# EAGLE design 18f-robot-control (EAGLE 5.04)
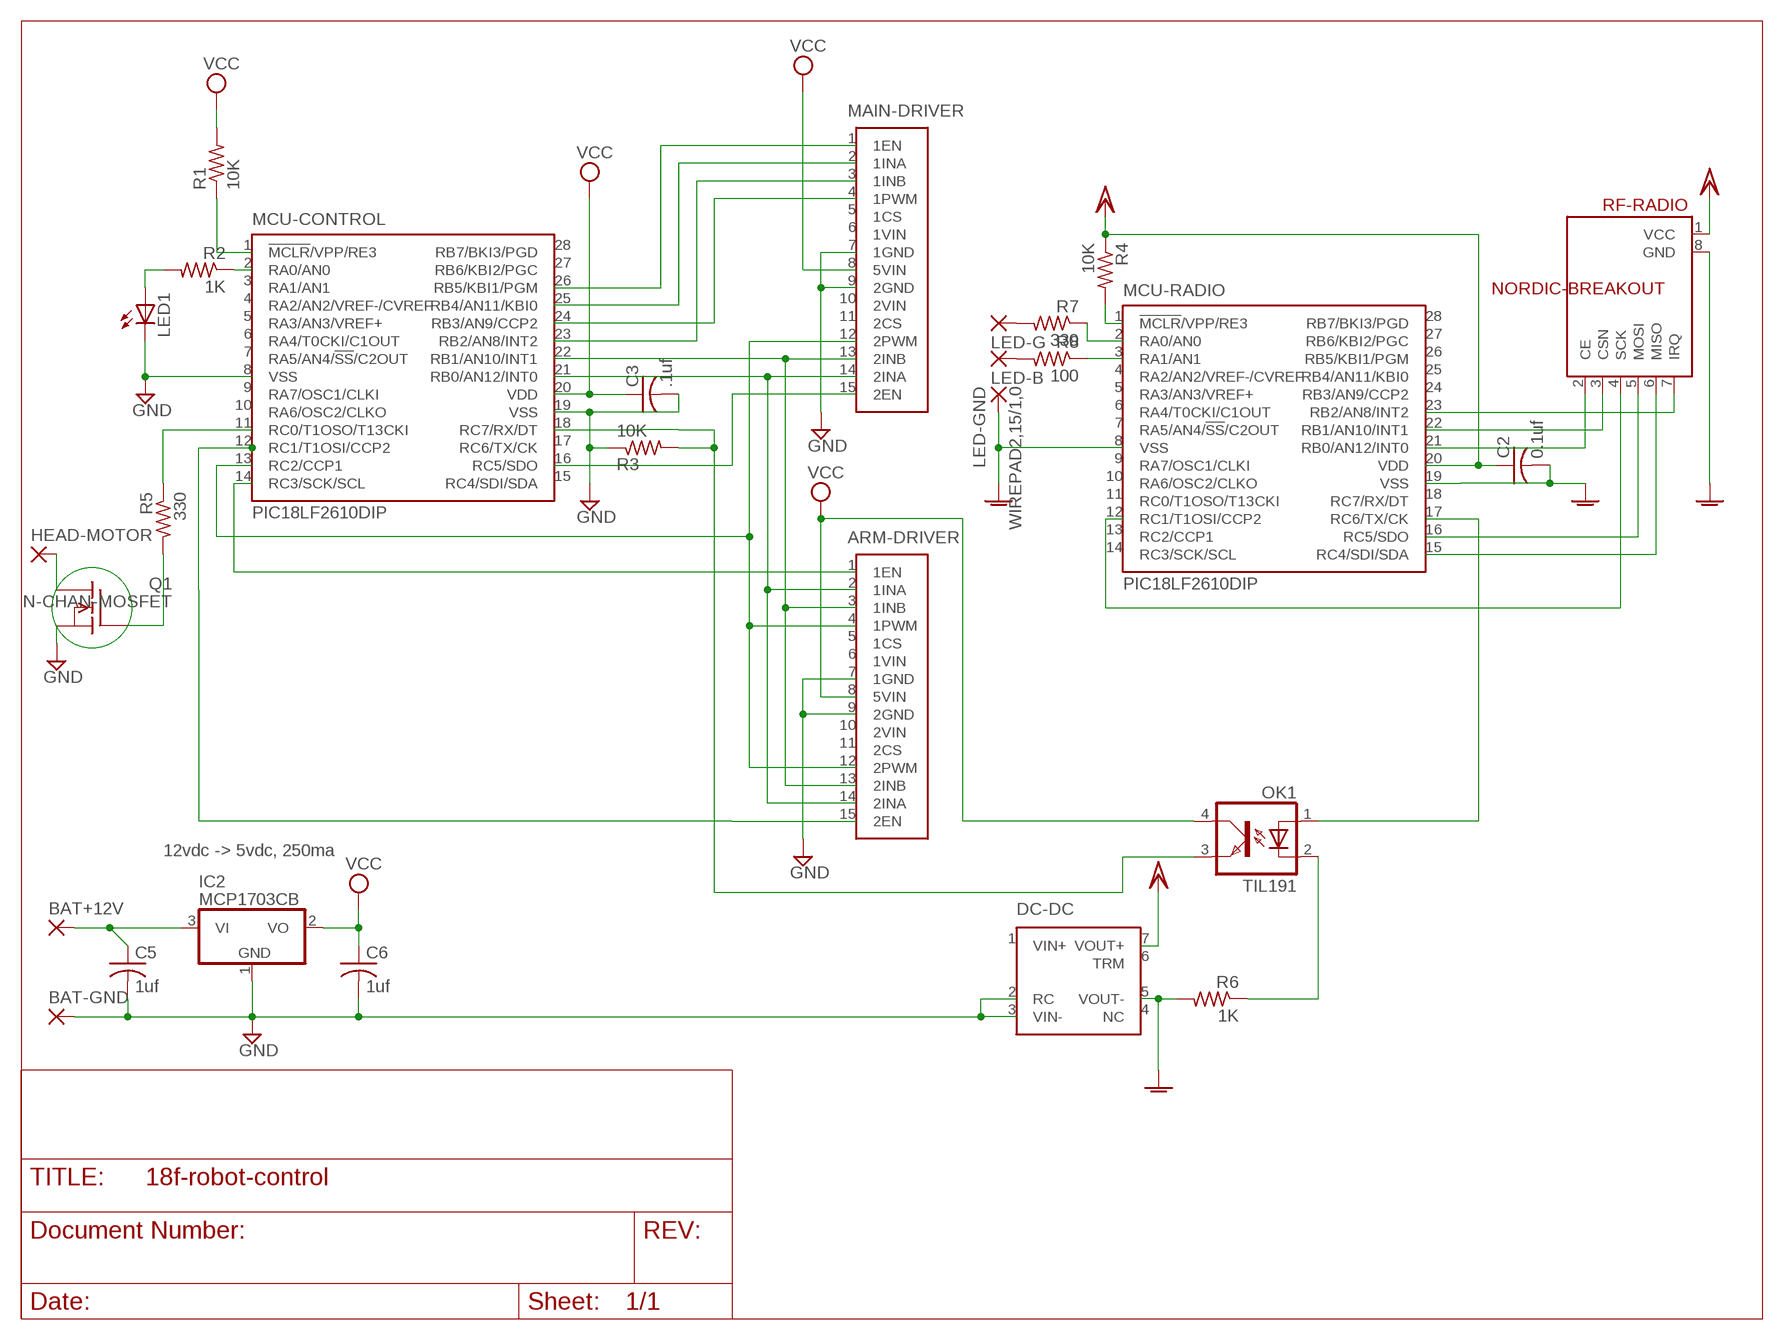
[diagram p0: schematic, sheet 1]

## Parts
ARM-DRIVER  POLOLU-DUAL-DRIVER-15ONLY  [15SIL]
BAT+12V  WIREPAD3,81/1,4  [3,81/1,4]
BAT-GND  WIREPAD3,81/1,4  [3,81/1,4]
C2  0.1uf  C-US050-030X075  [C050-030X075]
C3  .1uf  C-US025-030X050  [C025-030X050]
C5  1uf  C-US050-030X075  [C050-030X075]
C6  1uf  C-US050-030X075  [C050-030X075]
DC-DC  12V-5V-ISOLATED-DC-DC-TDK-LAMBDA  [DC-DC-12-5-TDK-LAMBDA]
HEAD-MOTOR  3,81/1,4  [3,81/1,4]
IC2  MCP1703CB  [SOT23]
LED1  LEDSFH480  [SFH480]
LED-B  WIREPAD2,15/1,0  [2,15/1,0]
LED-G  WIREPAD2,15/1,0  [2,15/1,0]
LED-GND  WIREPAD2,15/1,0  [2,15/1,0]
MAIN-DRIVER  POLOLU-DUAL-DRIVER-15ONLY  [15SIL]
MCU-CONTROL  PIC18LF2610DIP  [DIL28-3]
MCU-RADIO  PIC18LF2610DIP  [DIL28-3]
OK1  TIL191  [DIL04]
Q1  N-CHAN-MOSFET  SUP75N06-08  [TO220]
R1  10K  R-US_0204/7  [0204/7]
R2  1K  R-US_0204/7  [0204/7]
R3  10K  R-US_0204/7  [0204/7]
R4  10K  R-US_0204/7  [0204/7]
R5  330  R-US_0204/7  [0204/7]
R6  1K  R-US_0204/7  [0204/7]
R7  330  R-US_0204/7  [0204/7]
R8  100  R-US_0204/7  [0204/7]
RF-RADIO  NORDIC-BREAKOUT  [8SIL]

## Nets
GND: ARM-DRIVER.7(1GND) ARM-DRIVER.9(2GND) BAT-GND.1(P) C3.2 C5.2 C6.2 DC-DC.2(RC) DC-DC.3(VIN-) IC2.1(GND) LED1.K(C) MAIN-DRIVER.7(1GND) MAIN-DRIVER.9(2GND) MCU-CONTROL.8(VSS) MCU-CONTROL.19(VSS) Q1.3(S) R3.1
GND2: C2.2 DC-DC.5(VOUT-) LED-GND.1(P) MCU-RADIO.8(VSS) MCU-RADIO.19(VSS) R6.2 RF-RADIO.8(GND)
N$1: LED1.A R2.2
N$2: MCU-CONTROL.2(RA0/AN0) R2.1
N$3: HEAD-MOTOR.1(P) Q1.2(D)
N$4: ARM-DRIVER.15(2EN) MCU-CONTROL.12(RC1/T1OSI/CCP2)
N$5: MCU-CONTROL.11(RC0/T1OSO/T13CKI) R5.1
N$6: MCU-RADIO.2(RA0/AN0) R7.1
N$7: OK1.2(C) R6.1
N$8: MCU-RADIO.17(RC6/TX/CK) OK1.1(A)
N$9: MCU-CONTROL.18(RC7/RX/DT) OK1.3(EMIT) R3.2
N$10: MCU-RADIO.15(RC4/SDI/SDA) RF-RADIO.6(MISO)
N$11: MCU-RADIO.16(RC5/SDO) RF-RADIO.5(MOSI)
N$12: MAIN-DRIVER.4(1PWM) MCU-CONTROL.24(RB3/AN9/CCP2)
N$13: ARM-DRIVER.4(1PWM) ARM-DRIVER.12(2PWM) MAIN-DRIVER.12(2PWM) MCU-CONTROL.13(RC2/CCP1)
N$14: MCU-RADIO.12(RC1/T1OSI/CCP2) RF-RADIO.4(SCK)
N$15: ARM-DRIVER.1(1EN) MCU-CONTROL.14(RC3/SCK/SCL)
N$16: Q1.1(G) R5.2
N$17: MCU-RADIO.1(!MCLR!/VPP/RE3) R4.2
N$18: ARM-DRIVER.2(1INA) ARM-DRIVER.14(2INA) MAIN-DRIVER.14(2INA) MCU-CONTROL.21(RB0/AN12/INT0)
N$19: MCU-RADIO.22(RB1/AN10/INT1) RF-RADIO.3(CSN)
N$21: MAIN-DRIVER.2(1INA) MCU-CONTROL.25(RB4/AN11/KBI0)
N$22: MAIN-DRIVER.3(1INB) MCU-CONTROL.23(RB2/AN8/INT2)
N$23: MCU-RADIO.23(RB2/AN8/INT2) RF-RADIO.7(IRQ)
N$24: MAIN-DRIVER.15(2EN) MCU-CONTROL.16(RC5/SDO)
N$25: MCU-RADIO.21(RB0/AN12/INT0) RF-RADIO.2(CE)
N$26: MCU-RADIO.3(RA1/AN1) R8.1
N$28: MCU-CONTROL.1(!MCLR!/VPP/RE3) R1.1
N$31: MAIN-DRIVER.1(1EN) MCU-CONTROL.26(RB5/KBI1/PGM)
N$33: LED-G.1(P) R7.2
N$34: LED-B.1(P) R8.2
N$35: BAT+12V.1(P) C5.1 IC2.3(VI)
N$54: ARM-DRIVER.3(1INB) ARM-DRIVER.13(2INB) MAIN-DRIVER.13(2INB) MCU-CONTROL.22(RB1/AN10/INT1)
VCC: ARM-DRIVER.8(5VIN) C3.1 C6.1 IC2.2(VO) MAIN-DRIVER.8(5VIN) MCU-CONTROL.20(VDD) OK1.4(COL) R1.2
VCC2: C2.1 DC-DC.7(VOUT+) MCU-RADIO.20(VDD) R4.1 RF-RADIO.1(VCC)
Unconnected: ARM-DRIVER.5(1CS) ARM-DRIVER.6(1VIN) ARM-DRIVER.10(2VIN) ARM-DRIVER.11(2CS) DC-DC.1(VIN+) DC-DC.4(NC) DC-DC.6(TRM) MAIN-DRIVER.5(1CS) MAIN-DRIVER.6(1VIN) MAIN-DRIVER.10(2VIN) MAIN-DRIVER.11(2CS) MCU-CONTROL.3(RA1/AN1) MCU-CONTROL.4(RA2/AN2/VREF-/CVREF) MCU-CONTROL.5(RA3/AN3/VREF+) MCU-CONTROL.6(RA4/T0CKI/C1OUT) MCU-CONTROL.7(RA5/AN4/!SS!/C2OUT) MCU-CONTROL.9(RA7/OSC1/CLKI) MCU-CONTROL.10(RA6/OSC2/CLKO) MCU-CONTROL.15(RC4/SDI/SDA) MCU-CONTROL.17(RC6/TX/CK) MCU-CONTROL.27(RB6/KBI2/PGC) MCU-CONTROL.28(RB7/BKI3/PGD) MCU-RADIO.4(RA2/AN2/VREF-/CVREF) MCU-RADIO.5(RA3/AN3/VREF+) MCU-RADIO.6(RA4/T0CKI/C1OUT) MCU-RADIO.7(RA5/AN4/!SS!/C2OUT) MCU-RADIO.9(RA7/OSC1/CLKI) MCU-RADIO.10(RA6/OSC2/CLKO) MCU-RADIO.11(RC0/T1OSO/T13CKI) MCU-RADIO.13(RC2/CCP1) MCU-RADIO.14(RC3/SCK/SCL) MCU-RADIO.18(RC7/RX/DT) MCU-RADIO.24(RB3/AN9/CCP2) MCU-RADIO.25(RB4/AN11/KBI0) MCU-RADIO.26(RB5/KBI1/PGM) MCU-RADIO.27(RB6/KBI2/PGC) MCU-RADIO.28(RB7/BKI3/PGD)

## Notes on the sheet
- 12vdc -> 5vdc, 250ma

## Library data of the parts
ARM-DRIVER MAIN-DRIVER = trl:POLOLU-DUAL-DRIVER-15ONLY
BAT+12V BAT-GND LED-B LED-G LED-GND = wirepad:WIREPAD: Wire PAD connect wire on PCB
C2 C3 C5 C6 = rcl:C-US: CAPACITOR, American symbol
DC-DC = trl:12V-5V-ISOLATED-DC-DC-TDK-LAMBDA
HEAD-MOTOR = wirepad:3,81/1,4: THROUGH-HOLE PAD
IC2 = linear:MCP1703: 250 mA, 16V, Low Quiescent Current LDO Regulator Source: http://ww1.microchip.com/downloads/en/DeviceDoc/22049b.pdf
LED1 = led:LED: LED
MCU-CONTROL MCU-RADIO = trl:PIC18LF2610: PIC18LF2610 28-Pin, No USB or EEPROM
OK1 = optocoupler:TIL191: TEXAS INSTRUMENTS OPTO COUPLER
Q1 = transistor-fet:SUP75N06-08: N-Channel Enhancement MOSFET 60V; 75A; 0,008Ohm
R1-R8 = resistor:R-US_: RESISTOR, American symbol
RF-RADIO = trl:NORDIC-BREAKOUT: Spark Fun Electronic's Nordic Semiconductor nRF24L01 with chip antenna

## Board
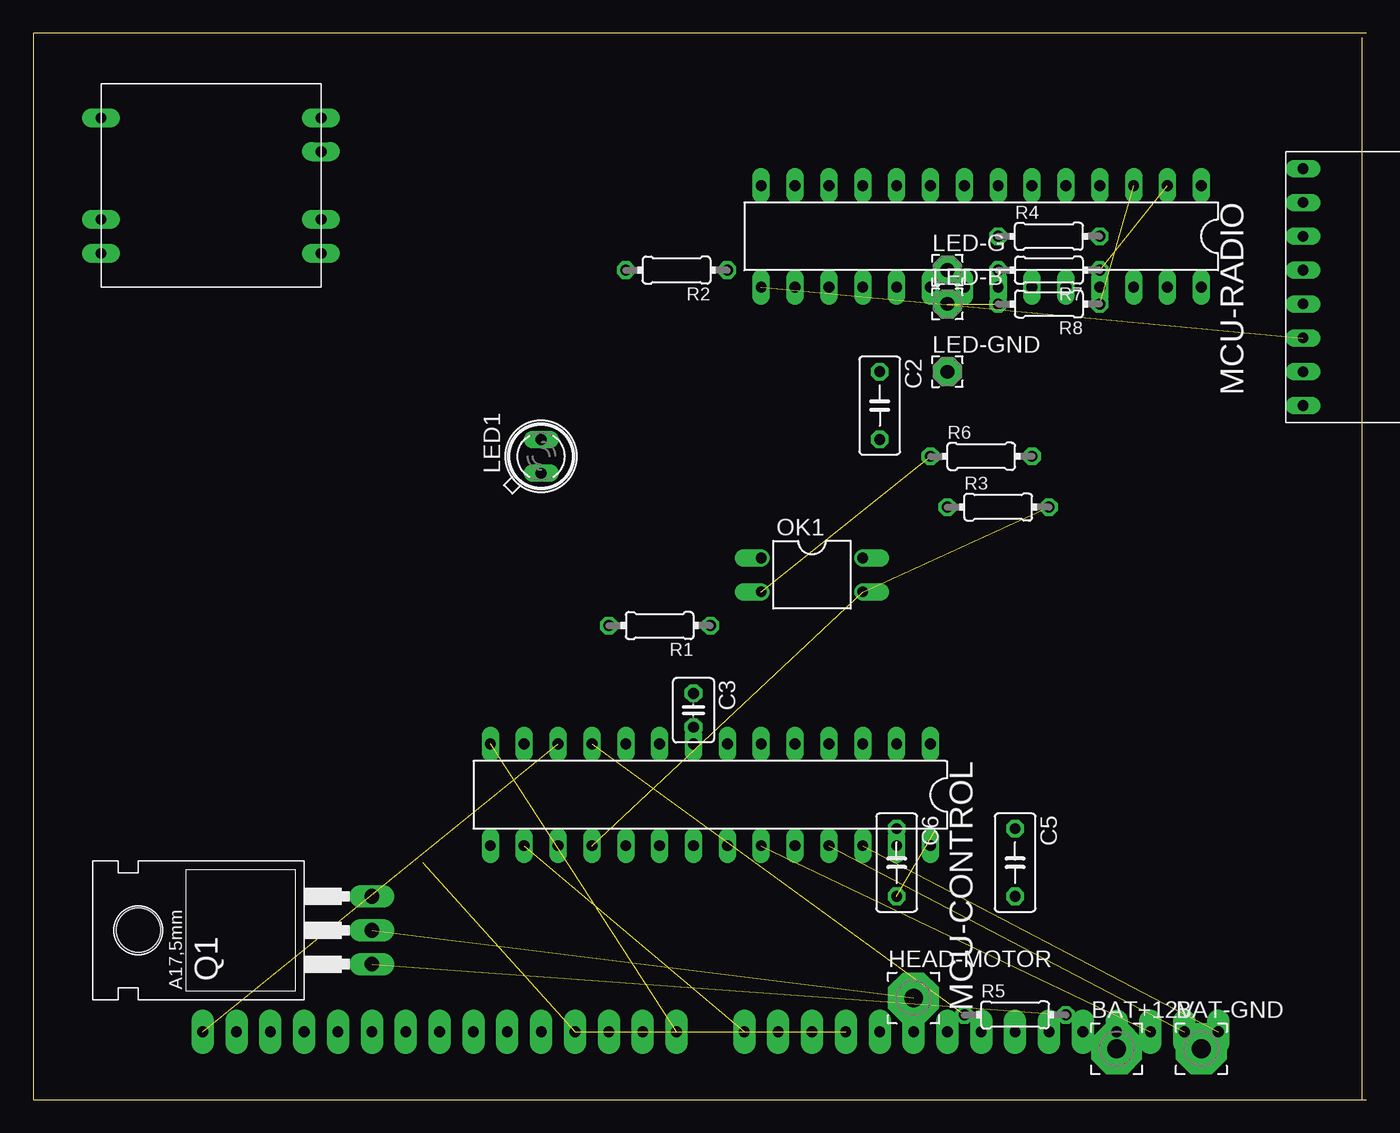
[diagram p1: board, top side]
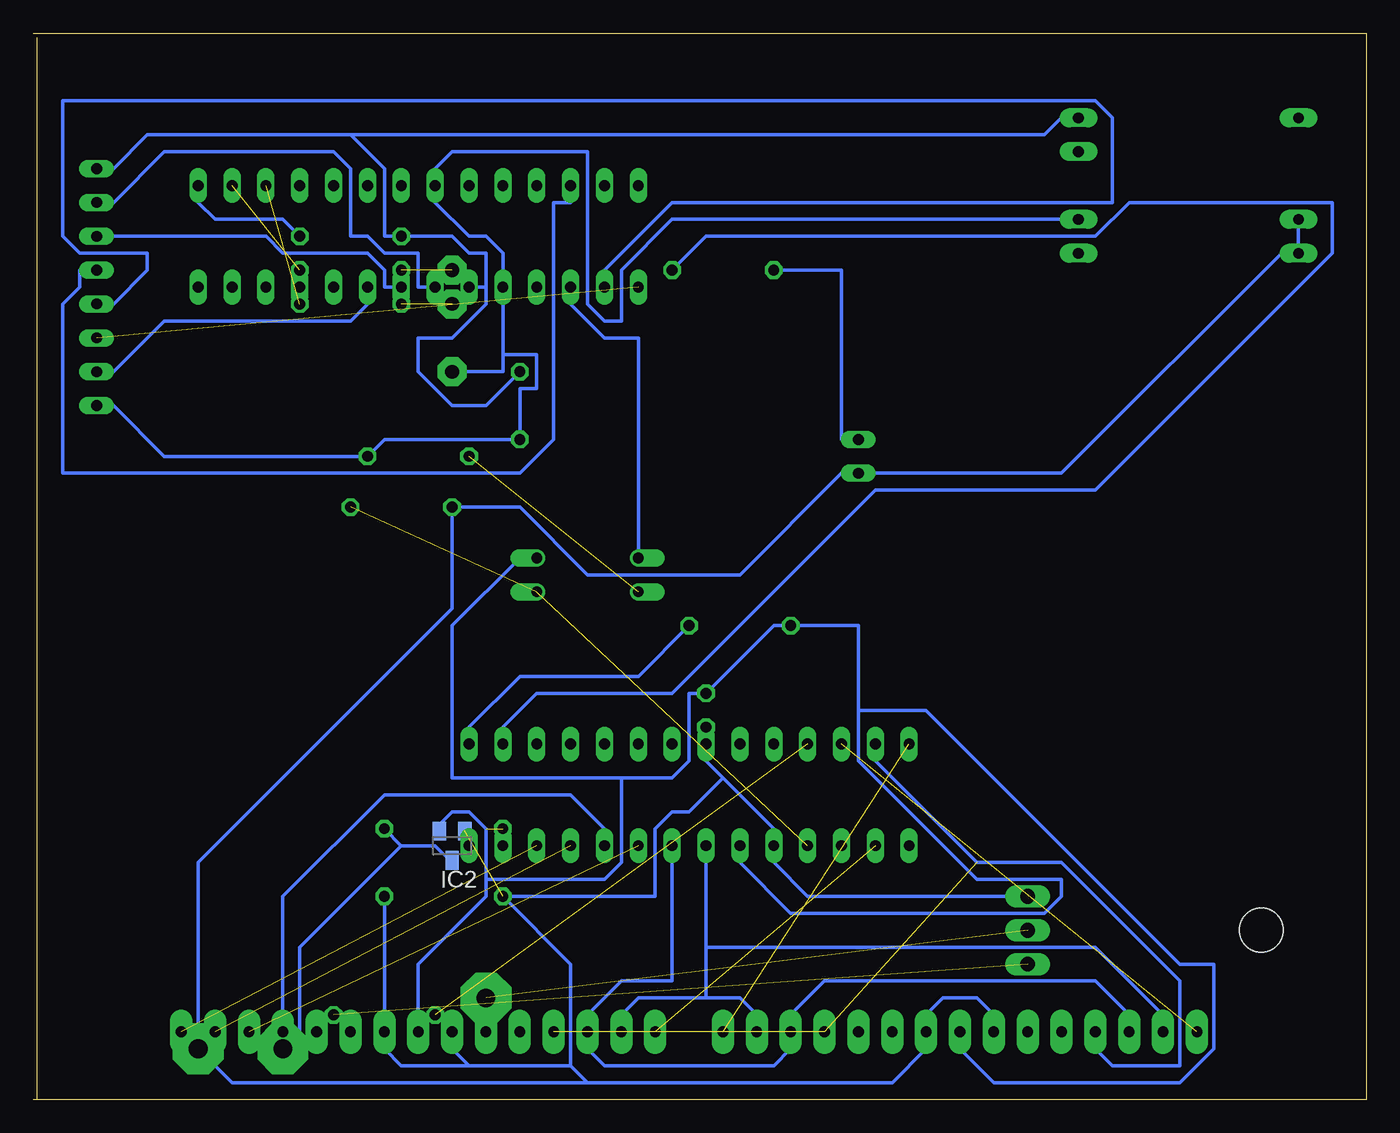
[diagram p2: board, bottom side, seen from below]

Size 100 x 80 mm. Coordinates in mm from the lower left corner, seen from the top.
Outline: 99.69,0 0,0 0,80 100,80
Outline: 99.69,0 100,0
Outline: 99.69,0 99.69,79.68
Copper layers (1*16): Top 0.035mm / dielectric 1.5mm / Bottom 0.035mm
Design rules "default": minimum track width 10mil, minimum drill 24mil, track to track 8mil, track to pad 8mil, pad to pad 8mil, via to via 8mil, smd to smd 8mil, copper to edge 40mil, drill to drill 8mil, minimum pad ring 10mil, minimum via ring 8mil, stop-mask expansion 4mil, vias tented up to drill 0mil, thermal gap 10mil

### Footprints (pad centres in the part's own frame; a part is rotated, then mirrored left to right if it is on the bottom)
15SIL = drill 0.8 pad 1.676 long: 1 -17.78,0; 2 -15.24,0; 3 -12.7,0; 4 -10.16,0; 5 -7.62,0; 6 -5.08,0; 7 -2.54,0; 8 0,0; 9 2.54,0; 10 5.08,0; 11 7.62,0; 12 10.16,0; 13 12.7,0; 14 15.24,0; 15 17.78,0
3,81/1,4 = drill 1.397 pad 3.81 octagon: 1 0,0
C050-030X075 = drill 0.813 octagon: 1 -2.54,0; 2 2.54,0
C025-030X050 = drill 0.813 octagon: 1 -1.27,0; 2 1.27,0
DC-DC-12-5-TDK-LAMBDA = drill 0.8 pad 1.422 long: 1 -8.89,5.08; 2 -8.89,-2.54; 3 -8.89,-5.08; 4 7.62,-5.08; 5 7.62,-2.54; 6 7.62,2.54; 7 7.62,5.08
SOT23 = smd 1 x 1.4: 1 -0.95,-1.1; 2 0.95,-1.1; 3 0,1.1
SFH480 = drill 0.813 long: A 1.27,0; K -1.27,0
2,15/1,0 = drill 1.016 pad 2.159 octagon: 1 0,0
DIL28-3 = drill 0.813 long: 1 -16.51,-3.81; 2 -13.97,-3.81; 3 -11.43,-3.81; 4 -8.89,-3.81; 5 -6.35,-3.81; 6 -3.81,-3.81; 7 -1.27,-3.81; 8 1.27,-3.81; 9 3.81,-3.81; 10 6.35,-3.81; 11 8.89,-3.81; 12 11.43,-3.81; 13 13.97,-3.81; 14 16.51,-3.81; 15 16.51,3.81; 16 13.97,3.81; 17 11.43,3.81; 18 8.89,3.81; 19 6.35,3.81; 20 3.81,3.81; 21 1.27,3.81; 22 -1.27,3.81; 23 -3.81,3.81; 24 -6.35,3.81; 25 -8.89,3.81; 26 -11.43,3.81; 27 -13.97,3.81; 28 -16.51,3.81
DIL04 = drill 0.813 offset: 1 -1.27,-3.81; 2 1.27,-3.81; 3 1.27,3.81; 4 -1.27,3.81
TO220 = drill 1.118 long: 1 -2.54,-6.35; 2 0,-6.35; 3 2.54,-6.35 | hole 3.302: 0,11.176
0204/7 = drill 0.813 octagon: 1 -3.81,0; 2 3.81,0
8SIL = drill 0.8 long: 1 -8.89,-8.89; 2 -6.35,-8.89; 3 -3.81,-8.89; 4 -1.27,-8.89; 5 1.27,-8.89; 6 3.81,-8.89; 7 6.35,-8.89; 8 8.89,-8.89

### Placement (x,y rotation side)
ARM-DRIVER  30.48,5.08 180 top
BAT+12V  81.28,3.81 0 top
BAT-GND  87.63,3.81 0 top
C2  63.5,52.07 270 top
C3  49.53,29.21 270 top
C5  73.66,17.78 270 top
C6  64.77,17.78 270 top
DC-DC  13.97,68.58 0 top
HEAD-MOTOR  66.04,7.62 0 top
IC2  68.58,19.05 180 bottom
LED1  38.1,48.26 90 top
LED-B  68.58,59.69 0 top
LED-G  68.58,62.23 0 top
LED-GND  68.58,54.61 0 top
MAIN-DRIVER  71.12,5.08 180 top
MCU-CONTROL  50.8,22.86 180 top
MCU-RADIO  71.12,64.77 180 top
OK1  58.42,39.37 270 top
Q1  19.05,12.7 90 top
R1  46.99,35.56 180 top
R2  48.26,62.23 180 top
R3  72.39,44.45 0 top
R4  76.2,64.77 0 top
R5  73.66,6.35 0 top
R6  71.12,48.26 0 top
R7  76.2,62.23 180 top
R8  76.2,59.69 180 top
RF-RADIO  104.14,60.96 270 top

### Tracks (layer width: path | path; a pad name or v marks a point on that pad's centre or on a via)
GND  (1 unrouted)
  Bottom 0.254: DC-DC.2 DC-DC.3 6.35,63.5 22.86,46.99 36.83,46.99 LED1.K 39.37,46.99 46.99,39.37 58.42,39.37 63.5,44.45 R3.1 68.58,36.83 87.63,17.78 87.63,5.08 BAT-GND.1 86.36,2.54 85.09,1.27 58.42,1.27 | 48.26,24.13 49.53,25.4 MCU-CONTROL.8 C3.2 | 48.26,24.13 44.45,20.32 MCU-CONTROL.19 44.45,17.78 41.91,15.24 26.67,15.24 Q1.3 | C5.2 73.66,6.35 MAIN-DRIVER.7 73.66,3.81 72.39,2.54 67.31,2.54 | ARM-DRIVER.9 27.94,6.35 29.21,7.62 31.75,7.62 33.02,6.35 ARM-DRIVER.7 33.02,3.81 35.56,1.27 58.42,1.27 | 59.69,2.54 59.69,10.16 C6.2 53.34,15.24 53.34,20.32 52.07,21.59 50.8,21.59 48.26,24.13 | 59.69,2.54 67.31,2.54 | 67.31,2.54 68.58,3.81 MAIN-DRIVER.9 | 58.42,1.27 59.69,2.54
GND2
  Bottom 0.254: RF-RADIO.8 93.98,52.07 90.17,48.26 R6.2 73.66,49.53 C2.2 63.5,53.34 62.23,53.34 62.23,55.88 64.77,55.88 | 64.77,55.88 64.77,54.61 LED-GND.1 | 64.77,55.88 64.77,59.69 MCU-RADIO.19 64.77,62.23 64.77,63.5 66.04,64.77 67.31,64.77 69.85,67.31 MCU-RADIO.8 69.85,69.85 68.58,71.12 58.42,71.12 58.42,59.69 57.15,58.42 55.88,58.42 55.88,62.23 52.07,66.04 22.86,66.04 DC-DC.5
N$1
  Bottom 0.254: R2.2 39.37,62.23 39.37,49.53 LED1.A
N$2
  Bottom 0.254: R2.1 49.53,64.77 20.32,64.77 17.78,67.31 2.54,67.31 2.54,63.5 20.32,45.72 36.83,45.72 52.07,30.48 62.23,30.48 64.77,27.94 MCU-CONTROL.2
N$3  (1 unrouted)
N$4  (1 unrouted)
N$5  (1 unrouted)
N$6  (1 unrouted)
N$7  (1 unrouted)
N$8
  Bottom 0.254: OK1.1 54.61,57.15 57.15,57.15 59.69,59.69 MCU-RADIO.17
N$9  (2 unrouted)
N$10  (1 unrouted)
N$11
  Bottom 0.254: RF-RADIO.5 93.98,59.69 91.44,62.23 91.44,63.5 96.52,63.5 97.79,64.77 97.79,74.93 20.32,74.93 19.05,73.66 19.05,67.31 52.07,67.31 57.15,62.23 MCU-RADIO.16
N$12
  Bottom 0.254: MCU-CONTROL.24 57.15,20.32 59.69,22.86 73.66,22.86 81.28,15.24 81.28,6.35 MAIN-DRIVER.4
N$13  (2 unrouted)
  Bottom 0.254: MCU-CONTROL.13 36.83,25.4 29.21,17.78 22.86,17.78 13.97,8.89 13.97,2.54 19.05,2.54 20.32,3.81 ARM-DRIVER.12
N$14
  Bottom 0.254: RF-RADIO.4 96.52,62.23 96.52,60.96 97.79,59.69 97.79,46.99 63.5,46.99 60.96,49.53 60.96,67.31 59.69,67.31 MCU-RADIO.12
N$15  (1 unrouted)
N$16  (1 unrouted)
N$17
  Bottom 0.254: R4.2 81.28,66.04 86.36,66.04 87.63,67.31 MCU-RADIO.1
N$18
  Bottom 0.254: 49.53,11.43 49.53,7.62 | 49.53,11.43 49.53,17.78 MCU-CONTROL.21 | 49.53,7.62 46.99,7.62 45.72,6.35 ARM-DRIVER.2 | 49.53,11.43 20.32,11.43 15.24,6.35 ARM-DRIVER.14 | 49.53,7.62 54.61,7.62 55.88,6.35 MAIN-DRIVER.14
N$19
  Bottom 0.254: MCU-RADIO.22 73.66,60.96 73.66,62.23 74.93,63.5 81.28,63.5 82.55,64.77 93.98,64.77 RF-RADIO.3
N$21  (1 unrouted)
N$22  (1 unrouted)
N$23
  Bottom 0.254: RF-RADIO.7 93.98,54.61 90.17,58.42 76.2,58.42 74.93,59.69 MCU-RADIO.23
N$24  (1 unrouted)
N$25
  Bottom 0.254: MCU-RADIO.21 71.12,60.96 71.12,63.5 73.66,63.5 74.93,64.77 76.2,64.77 76.2,69.85 77.47,71.12 90.17,71.12 93.98,67.31 RF-RADIO.2
N$26  (1 unrouted)
N$28
  Bottom 0.254: R1.1 54.61,31.75 63.5,31.75 67.31,27.94 MCU-CONTROL.1
N$31  (1 unrouted)
N$33  (1 unrouted)
N$34  (1 unrouted)
N$35
  Bottom 0.254: 72.39,19.05 69.85,19.05 68.58,17.78 IC2.3 | 72.39,19.05 C5.1 | 72.39,19.05 80.01,11.43 80.01,5.08 BAT+12V.1
N$54
  Bottom 0.254: MCU-CONTROL.22 52.07,17.78 52.07,8.89 55.88,8.89 58.42,6.35 MAIN-DRIVER.13 58.42,3.81 57.15,2.54 44.45,2.54 43.18,3.81 ARM-DRIVER.3 43.18,6.35 40.64,8.89 20.32,8.89 17.78,6.35 ARM-DRIVER.13
VCC  (1 unrouted)
  Bottom 0.254: 66.04,16.51 66.04,15.24 71.12,10.16 71.12,6.35 MAIN-DRIVER.8 | 66.04,16.51 66.04,20.32 67.31,21.59 68.58,21.59 69.85,20.32 IC2.2 | 38.1,29.21 38.1,35.56 R1.2 44.45,35.56 C3.1 50.8,30.48 50.8,25.4 52.07,24.13 55.88,24.13 | 38.1,29.21 38.1,25.4 29.21,16.51 22.86,16.51 22.86,15.24 24.13,13.97 43.18,13.97 46.99,17.78 MCU-CONTROL.20 | 55.88,24.13 68.58,24.13 68.58,35.56 63.5,40.64 OK1.4 | 38.1,29.21 33.02,29.21 13.97,10.16 11.43,10.16 11.43,3.81 13.97,1.27 27.94,1.27 30.48,3.81 ARM-DRIVER.8 | 66.04,16.51 57.15,16.51 55.88,17.78 55.88,24.13
VCC2
  Bottom 0.254: C2.1 66.04,52.07 68.58,52.07 71.12,54.61 71.12,57.15 68.58,57.15 66.04,59.69 66.04,60.96 | 66.04,60.96 MCU-RADIO.20 | 76.2,72.39 91.44,72.39 93.98,69.85 RF-RADIO.1 | 76.2,72.39 73.66,69.85 73.66,64.77 R4.1 68.58,64.77 67.31,63.5 66.04,63.5 66.04,60.96 | 76.2,72.39 24.13,72.39 22.86,73.66 DC-DC.7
